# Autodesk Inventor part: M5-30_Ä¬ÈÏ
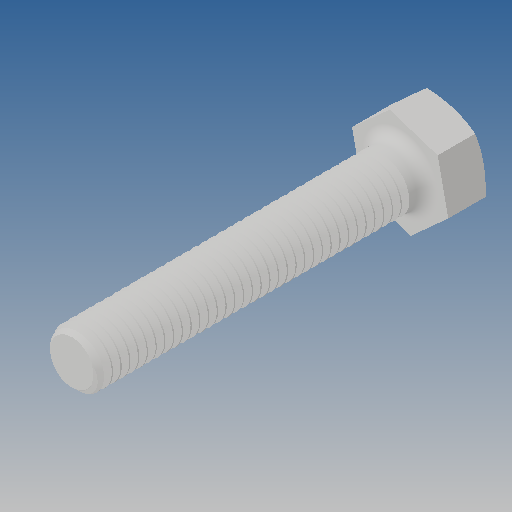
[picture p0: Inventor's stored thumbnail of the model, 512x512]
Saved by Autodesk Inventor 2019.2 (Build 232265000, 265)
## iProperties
Created: 2010-06
Part Number: M5-30_Ä¬ÈÏ
Material: Ogólny
Document SubType Name: Modeling
Designer: CADENGINEERING4
Density: 1 g/cm^3
Appearance: Domyślna
Author: CADENGINEERING4
Revision Number: ÈÎºÎ
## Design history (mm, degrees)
feature "NONE"
node "Bryła1"
